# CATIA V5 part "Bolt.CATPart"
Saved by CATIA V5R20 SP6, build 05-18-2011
Part number: Bolt(M8X1.25)
Bounding box of the stored display mesh (mm): x -5.474 to 5.474, y 1.5 to 38.02, z -5.474 to 5.474
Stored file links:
  E:\#01 CATIA Lecture Materials\#06 DMU\#05 DMU Page01 KIN EX05\Bolt.CATPart
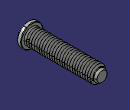
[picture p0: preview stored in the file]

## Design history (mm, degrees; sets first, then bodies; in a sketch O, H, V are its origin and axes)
Body1 (main body)
Body2 "Bolt"
  Solid1: solid without history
